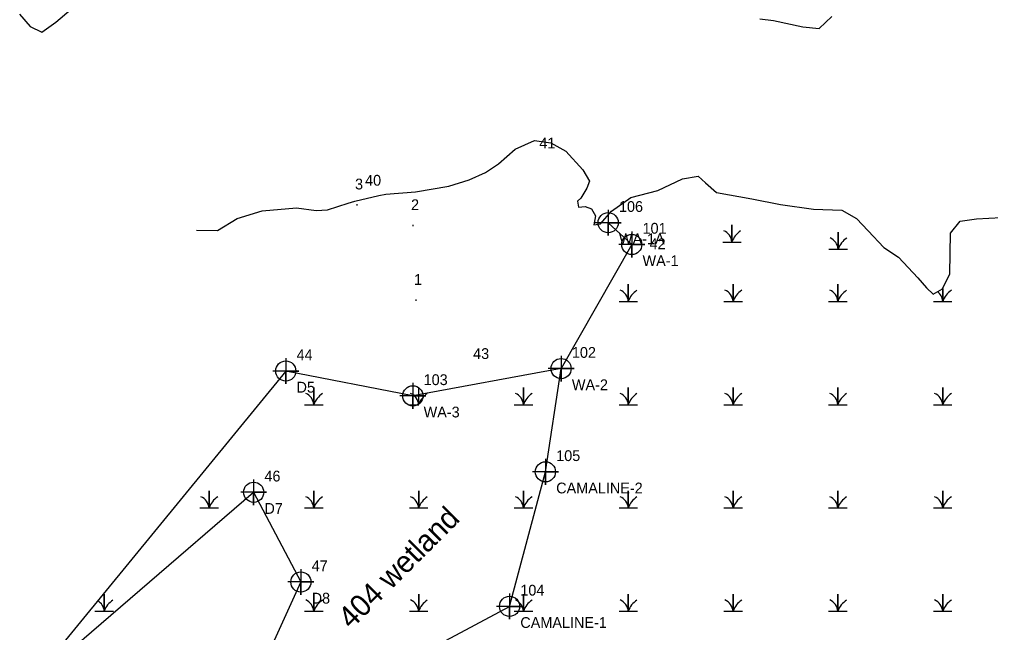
# Model space of a CAD drawing. Extents: x 2678633 to 2679425, y 623836 to 624637.
# Drawn here: x 2678912.6 to 2679137.9, y 624022.3 to 624164.5 of the extents above; entities that cross this region are included whole.
import ezdxf

# ---------------------------------------------------------------- set-up
doc = ezdxf.new("R2010")
doc.units = 0
for name, color, linetype in [('Exist Environmental Wetland Boundary', 7, 'Continuous'), ('Exist Environmental Wetland Boundary Cogo Comment', 7, 'Continuous'), ('Exist Environmental Wetland Boundary Cogo Elevation', 7, 'Continuous'), ('Exist Environmental Wetland Boundary Cogo Number', 7, 'Continuous'), ('Exist Environmental Wetland Boundary Cogo Point CELL', 7, 'Continuous'), ('Exist Environmental Wetland Boundary Text', 7, 'Continuous'), ('Exist Hydro Jurisdictional Stream or Body of Water NEU Mitigable', 7, 'Continuous'), ('Exist Hydro Swamp or Marsh', 7, 'Continuous')]:
    doc.layers.add(name, color=color, linetype=linetype)

msp = doc.modelspace()

# ---------------------------------------------------------------- linework, layer by layer
at = {"layer": 'Exist Environmental Wetland Boundary'}
for points in [[(2679049.19, 624117.35), (2679054.66, 624112.3), (2679038.27, 624083.52), (2679003.88, 624077.2), (2678974.4, 624082.96)], [(2678974.4, 624082.96), (2678914.21, 624009.47), (2678966.95, 624054.85), (2678977.91, 624034.05), (2678957.81, 623989.86), (2678920.96, 623978.51), (2678926.32, 623954.76), (2678939.29, 623961), (2678977.9, 623990.4), (2679003.55, 624016.25)], [(2679003.55, 624016.25), (2679026.31, 624028.4), (2679034.63, 624059.59), (2679038.27, 624083.52)]]:
    msp.add_lwpolyline(points, dxfattribs=at)
at = {"layer": 'Exist Environmental Wetland Boundary Cogo Point CELL'}
for points in [[(2679049.19, 624120.35), (2679049.19, 624114.35), (2679049.19, 624117.35), (2679052.19, 624117.35), (2679046.19, 624117.35)], [(2679054.66, 624115.3), (2679054.66, 624109.3), (2679054.66, 624112.3), (2679057.66, 624112.3), (2679051.66, 624112.3)], [(2678974.4, 624085.96), (2678974.4, 624079.96), (2678974.4, 624082.96), (2678977.4, 624082.96), (2678971.4, 624082.96)], [(2679038.27, 624086.52), (2679038.27, 624080.52), (2679038.27, 624083.52), (2679041.27, 624083.52), (2679035.27, 624083.52)], [(2679003.88, 624080.2), (2679003.88, 624074.2), (2679003.88, 624077.2), (2679006.88, 624077.2), (2679000.88, 624077.2)], [(2679034.63, 624062.59), (2679034.63, 624056.59), (2679034.63, 624059.59), (2679037.63, 624059.59), (2679031.63, 624059.59)], [(2678966.95, 624057.85), (2678966.95, 624051.85), (2678966.95, 624054.85), (2678969.95, 624054.85), (2678963.95, 624054.85)], [(2678977.91, 624037.05), (2678977.91, 624031.05), (2678977.91, 624034.05), (2678980.91, 624034.05), (2678974.91, 624034.05)], [(2679026.31, 624031.4), (2679026.31, 624025.4), (2679026.31, 624028.4), (2679029.31, 624028.4), (2679023.31, 624028.4)]]:
    msp.add_lwpolyline(points, dxfattribs=at)
for centre in [(2679049.19, 624117.35), (2679054.66, 624112.3), (2679038.27, 624083.52), (2678974.4, 624082.96), (2679003.88, 624077.2), (2679034.63, 624059.59), (2678966.95, 624054.85), (2678977.91, 624034.05), (2679026.31, 624028.4)]:
    msp.add_circle(centre, 2.34, dxfattribs=at)
at = {"layer": 'Exist Hydro Jurisdictional Stream or Body of Water NEU Mitigable'}
msp.add_line((2678990.44, 624122.31), (2678995.99, 624123.64), dxfattribs=at)
for points in [[(2678912.62, 624165.68), (2678915.12, 624162.85), (2678917.83, 624161.52), (2678921.06, 624163.85), (2678924.65, 624166.83)], [(2679084.39, 624164.62), (2679087.52, 624164.2), (2679094.37, 624162.74), (2679098.12, 624162.41), (2679101.05, 624165.19)], [(2678995.99, 624123.64), (2678997.65, 624123.98), (2679004.5, 624124.49), (2679012.25, 624125.83), (2679016.94, 624127.26), (2679020.7, 624128.95), (2679023.77, 624130.98), (2679027.62, 624134.39), (2679032.1, 624136.44), (2679035.89, 624135.87), (2679039.39, 624133.95), (2679043.3, 624129.62), (2679044.89, 624127.01), (2679044.26, 624125.36), (2679042.85, 624123.04), (2679042.08, 624122.36), (2679042.29, 624120.94), (2679043.86, 624121.13), (2679045.34, 624120.58), (2679046.23, 624118.96), (2679045.87, 624116.87), (2679047.37, 624117.11), (2679049.92, 624120.05), (2679054.41, 624123.18), (2679060.73, 624124.78), (2679066.42, 624127.49), (2679070.09, 624128.16), (2679071.75, 624126.57), (2679074.28, 624124.37), (2679082.5, 624122.9), (2679089.18, 624121.59), (2679096.85, 624120.5), (2679103.39, 624120.26), (2679106.82, 624118.36), (2679109.46, 624115.44), (2679113.13, 624111.63), (2679116.54, 624109.35), (2679120.98, 624104.53), (2679123.02, 624102.22), (2679124.54, 624100.79), (2679126.74, 624101.98), (2679128.41, 624105.48), (2679128.49, 624110.17), (2679128.6, 624114.95), (2679130.86, 624117.71), (2679134.61, 624118.28), (2679140.32, 624118.54)], [(2678953.66, 624115.61), (2678958.56, 624115.56), (2678963.09, 624118.34), (2678968.9, 624120.11), (2678976.87, 624120.81), (2678981.43, 624120.14), (2678984.09, 624120.36), (2678988.91, 624121.91), (2678990.44, 624122.31)]]:
    msp.add_lwpolyline(points, dxfattribs=at)
at = {"layer": 'Exist Hydro Swamp or Marsh'}
for p, q in [((2679077.9, 624114.66), (2679077.9, 624114.66)), ((2679102.53, 624112.99), (2679102.53, 624112.99))]:
    msp.add_line(p, q, dxfattribs=at)
for points in [[(2679075.75, 624112.87), (2679077.9, 624112.87), (2679077.9, 624116.82), (2679077.9, 624112.87), (2679080.05, 624112.87)], [(2679100.38, 624111.21), (2679102.54, 624111.21), (2679102.54, 624115.15), (2679102.54, 624111.21), (2679104.69, 624111.21)], [(2679051.7, 624099.11), (2679053.86, 624099.11), (2679053.86, 624103.06), (2679053.86, 624099.11), (2679056.01, 624099.11)], [(2679076.02, 624099.11), (2679078.17, 624099.11), (2679078.17, 624103.06), (2679078.17, 624099.11), (2679080.32, 624099.11)], [(2679100.33, 624099.11), (2679102.48, 624099.11), (2679102.48, 624103.06), (2679102.48, 624099.11), (2679104.63, 624099.11)], [(2679124.64, 624099.11), (2679126.79, 624099.11), (2679126.79, 624102.1)], [(2679126.79, 624102.1), (2679126.79, 624099.11), (2679128.94, 624099.11)], [(2678978.77, 624075.16), (2678980.92, 624075.16), (2678980.92, 624079.11), (2678980.92, 624075.16), (2678983.07, 624075.16)], [(2679003.08, 624075.16), (2679005.23, 624075.16), (2679005.23, 624079.11)], [(2679027.39, 624075.16), (2679029.54, 624075.16), (2679029.54, 624079.11), (2679029.54, 624075.16), (2679031.69, 624075.16)], [(2679051.7, 624075.16), (2679053.86, 624075.16), (2679053.86, 624079.11), (2679053.86, 624075.16), (2679056.01, 624075.16)], [(2679076.02, 624075.16), (2679078.17, 624075.16), (2679078.17, 624079.11), (2679078.17, 624075.16), (2679080.32, 624075.16)], [(2679100.33, 624075.16), (2679102.48, 624075.16), (2679102.48, 624079.11), (2679102.48, 624075.16), (2679104.63, 624075.16)], [(2679124.64, 624075.16), (2679126.79, 624075.16), (2679126.79, 624079.11), (2679126.79, 624075.16), (2679128.94, 624075.16)], [(2678954.45, 624051.21), (2678956.61, 624051.21), (2678956.61, 624055.16), (2678956.61, 624051.21), (2678958.76, 624051.21)], [(2678978.77, 624051.21), (2678980.92, 624051.21), (2678980.92, 624055.16), (2678980.92, 624051.21), (2678983.07, 624051.21)], [(2679003.08, 624051.21), (2679005.23, 624051.21), (2679005.23, 624055.16), (2679005.23, 624051.21), (2679007.38, 624051.21)], [(2679027.39, 624051.21), (2679029.54, 624051.21), (2679029.54, 624055.16), (2679029.54, 624051.21), (2679031.69, 624051.21)], [(2679051.7, 624051.21), (2679053.86, 624051.21), (2679053.86, 624055.16), (2679053.86, 624051.21), (2679056.01, 624051.21)], [(2679076.02, 624051.21), (2679078.17, 624051.21), (2679078.17, 624055.16), (2679078.17, 624051.21), (2679080.32, 624051.21)], [(2679100.33, 624051.21), (2679102.48, 624051.21), (2679102.48, 624055.16), (2679102.48, 624051.21), (2679104.63, 624051.21)], [(2679124.64, 624051.21), (2679126.79, 624051.21), (2679126.79, 624055.16), (2679126.79, 624051.21), (2679128.94, 624051.21)], [(2678930.14, 624027.26), (2678932.29, 624027.26), (2678932.29, 624031.21), (2678932.29, 624027.26), (2678934.44, 624027.26)], [(2678978.77, 624027.26), (2678980.92, 624027.26), (2678980.92, 624031.21), (2678980.92, 624027.26), (2678983.07, 624027.26)], [(2679003.08, 624027.26), (2679005.23, 624027.26), (2679005.23, 624031.21), (2679005.23, 624027.26), (2679007.38, 624027.26)], [(2679027.39, 624027.26), (2679029.54, 624027.26), (2679029.54, 624031.21), (2679029.54, 624027.26), (2679031.69, 624027.26)], [(2679051.7, 624027.26), (2679053.86, 624027.26), (2679053.86, 624031.21), (2679053.86, 624027.26), (2679056.01, 624027.26)], [(2679076.02, 624027.26), (2679078.17, 624027.26), (2679078.17, 624031.21), (2679078.17, 624027.26), (2679080.32, 624027.26)], [(2679100.33, 624027.26), (2679102.48, 624027.26), (2679102.48, 624031.21), (2679102.48, 624027.26), (2679104.63, 624027.26)], [(2679124.64, 624027.26), (2679126.79, 624027.26), (2679126.79, 624031.21), (2679126.79, 624027.26), (2679128.94, 624027.26)]]:
    msp.add_lwpolyline(points, dxfattribs=at)
for centre, radius, start, end in [((2679074.83, 624112.65), 3.07, 4.1403, 67.535), ((2679082.46, 624111.36), 4.81, 122.1274, 161.6222), ((2679099.47, 624110.98), 3.07, 4.1403, 67.535), ((2679107.1, 624109.69), 4.81, 122.1274, 161.6222), ((2679050.79, 624098.89), 3.07, 4.1403, 67.535), ((2679058.42, 624097.6), 4.81, 122.1274, 161.6222), ((2679075.1, 624098.89), 3.07, 4.1403, 67.535), ((2679082.73, 624097.6), 4.81, 122.1274, 161.6222), ((2679099.41, 624098.89), 3.07, 4.1403, 67.535), ((2679107.04, 624097.6), 4.81, 122.1274, 161.6222), ((2679131.35, 624097.6), 4.81, 122.1274, 161.6222), ((2679123.73, 624098.89), 3.07, 4.1403, 53.1617), ((2678977.85, 624074.94), 3.07, 4.1403, 67.535), ((2678985.48, 624073.65), 4.81, 122.1274, 161.6222), ((2679002.16, 624074.94), 3.07, 4.1403, 67.535), ((2679009.79, 624073.65), 4.81, 122.1274, 161.6222), ((2679026.48, 624074.94), 3.07, 4.1403, 67.535), ((2679034.1, 624073.65), 4.81, 122.1274, 161.6222), ((2679050.79, 624074.94), 3.07, 4.1403, 67.535), ((2679058.42, 624073.65), 4.81, 122.1274, 161.6222), ((2679075.1, 624074.94), 3.07, 4.1403, 67.535), ((2679082.73, 624073.65), 4.81, 122.1274, 161.6222), ((2679099.41, 624074.94), 3.07, 4.1403, 67.535), ((2679107.04, 624073.65), 4.81, 122.1274, 161.6222), ((2679123.73, 624074.94), 3.07, 4.1403, 67.535), ((2679131.35, 624073.65), 4.81, 122.1274, 161.6222), ((2678953.54, 624050.99), 3.07, 4.1403, 67.535), ((2678961.17, 624049.7), 4.81, 122.1274, 161.6222), ((2678977.85, 624050.99), 3.07, 4.1403, 67.535), ((2678985.48, 624049.7), 4.81, 122.1274, 161.6222), ((2679002.16, 624050.99), 3.07, 4.1403, 67.535), ((2679009.79, 624049.7), 4.81, 122.1274, 161.6222), ((2679026.48, 624050.99), 3.07, 4.1403, 67.535), ((2679034.1, 624049.7), 4.81, 122.1274, 161.6222), ((2679050.79, 624050.99), 3.07, 4.1403, 67.535), ((2679058.42, 624049.7), 4.81, 122.1274, 161.6222), ((2679075.1, 624050.99), 3.07, 4.1403, 67.535), ((2679082.73, 624049.7), 4.81, 122.1274, 161.6222), ((2679099.41, 624050.99), 3.07, 4.1403, 67.535), ((2679107.04, 624049.7), 4.81, 122.1274, 161.6222), ((2679123.73, 624050.99), 3.07, 4.1403, 67.535), ((2679131.35, 624049.7), 4.81, 122.1274, 161.6222), ((2678929.23, 624027.04), 3.07, 4.1403, 59.757), ((2678936.85, 624025.75), 4.81, 122.1274, 161.6222), ((2678977.85, 624027.04), 3.07, 4.1403, 67.535), ((2678985.48, 624025.75), 4.81, 122.1274, 161.6222), ((2679002.16, 624027.04), 3.07, 4.1403, 67.535), ((2679009.79, 624025.75), 4.81, 122.1274, 161.6222), ((2679026.48, 624027.04), 3.07, 4.1403, 67.535), ((2679034.1, 624025.75), 4.81, 122.1274, 161.6222), ((2679050.79, 624027.04), 3.07, 4.1403, 67.535), ((2679058.42, 624025.75), 4.81, 122.1274, 161.6222), ((2679075.1, 624027.04), 3.07, 4.1403, 67.535), ((2679082.73, 624025.75), 4.81, 122.1274, 161.6222), ((2679099.41, 624027.04), 3.07, 4.1403, 67.535), ((2679107.04, 624025.75), 4.81, 122.1274, 161.6222), ((2679123.73, 624027.04), 3.07, 4.1403, 67.535), ((2679131.35, 624025.75), 4.81, 122.1274, 161.6222)]:
    msp.add_arc(centre, radius, start, end, dxfattribs=at)

# ---------------------------------------------------------------- texts
at = {"layer": 'Exist Environmental Wetland Boundary Cogo Comment'}
for s, p in [('WA-1A', (2679051.69, 624112.35)), ('WA-1', (2679057.16, 624107.3)), ('D5', (2678976.9, 624077.96)), ('WA-2', (2679040.77, 624078.52)), ('WA-3', (2679006.38, 624072.2)), ('CAMALINE-2', (2679037.13, 624054.59)), ('D7', (2678969.45, 624049.85)), ('D8', (2678980.41, 624029.05)), ('CAMALINE-1', (2679028.81, 624023.4))]:
    msp.add_text(s, height=2.5, dxfattribs=at).set_placement(p)
at = {"layer": 'Exist Environmental Wetland Boundary Cogo Elevation'}
for p in [(2678990.47, 624121.31), (2679003.46, 624116.52), (2679004.15, 624099.18)]:
    msp.add_text('.', height=2.5, dxfattribs=at).set_placement(p)
at = {"layer": 'Exist Environmental Wetland Boundary Cogo Number'}
for s, p in [('41', (2679033.23, 624134.57)), ('3', (2678990.47, 624125.06)), ('40', (2678992.8, 624125.93)), ('2', (2679003.46, 624120.27)), ('106', (2679051.69, 624119.85)), ('101', (2679057.16, 624114.8)), ('42', (2679058.78, 624111.2)), ('1', (2679004.15, 624102.93)), ('43', (2679017.86, 624085.75)), ('102', (2679040.77, 624086.02)), ('44', (2678976.9, 624085.46)), ('103', (2679006.38, 624079.7)), ('105', (2679037.13, 624062.09)), ('46', (2678969.45, 624057.35)), ('47', (2678980.41, 624036.55)), ('104', (2679028.81, 624030.9))]:
    msp.add_text(s, height=2.5, dxfattribs=at).set_placement(p)
at = {"layer": 'Exist Environmental Wetland Boundary Text'}
msp.add_text('404 wetland', height=5, rotation=45, dxfattribs=at).set_placement((2678989.56, 624022.93))

doc.saveas('drawing.dxf')
